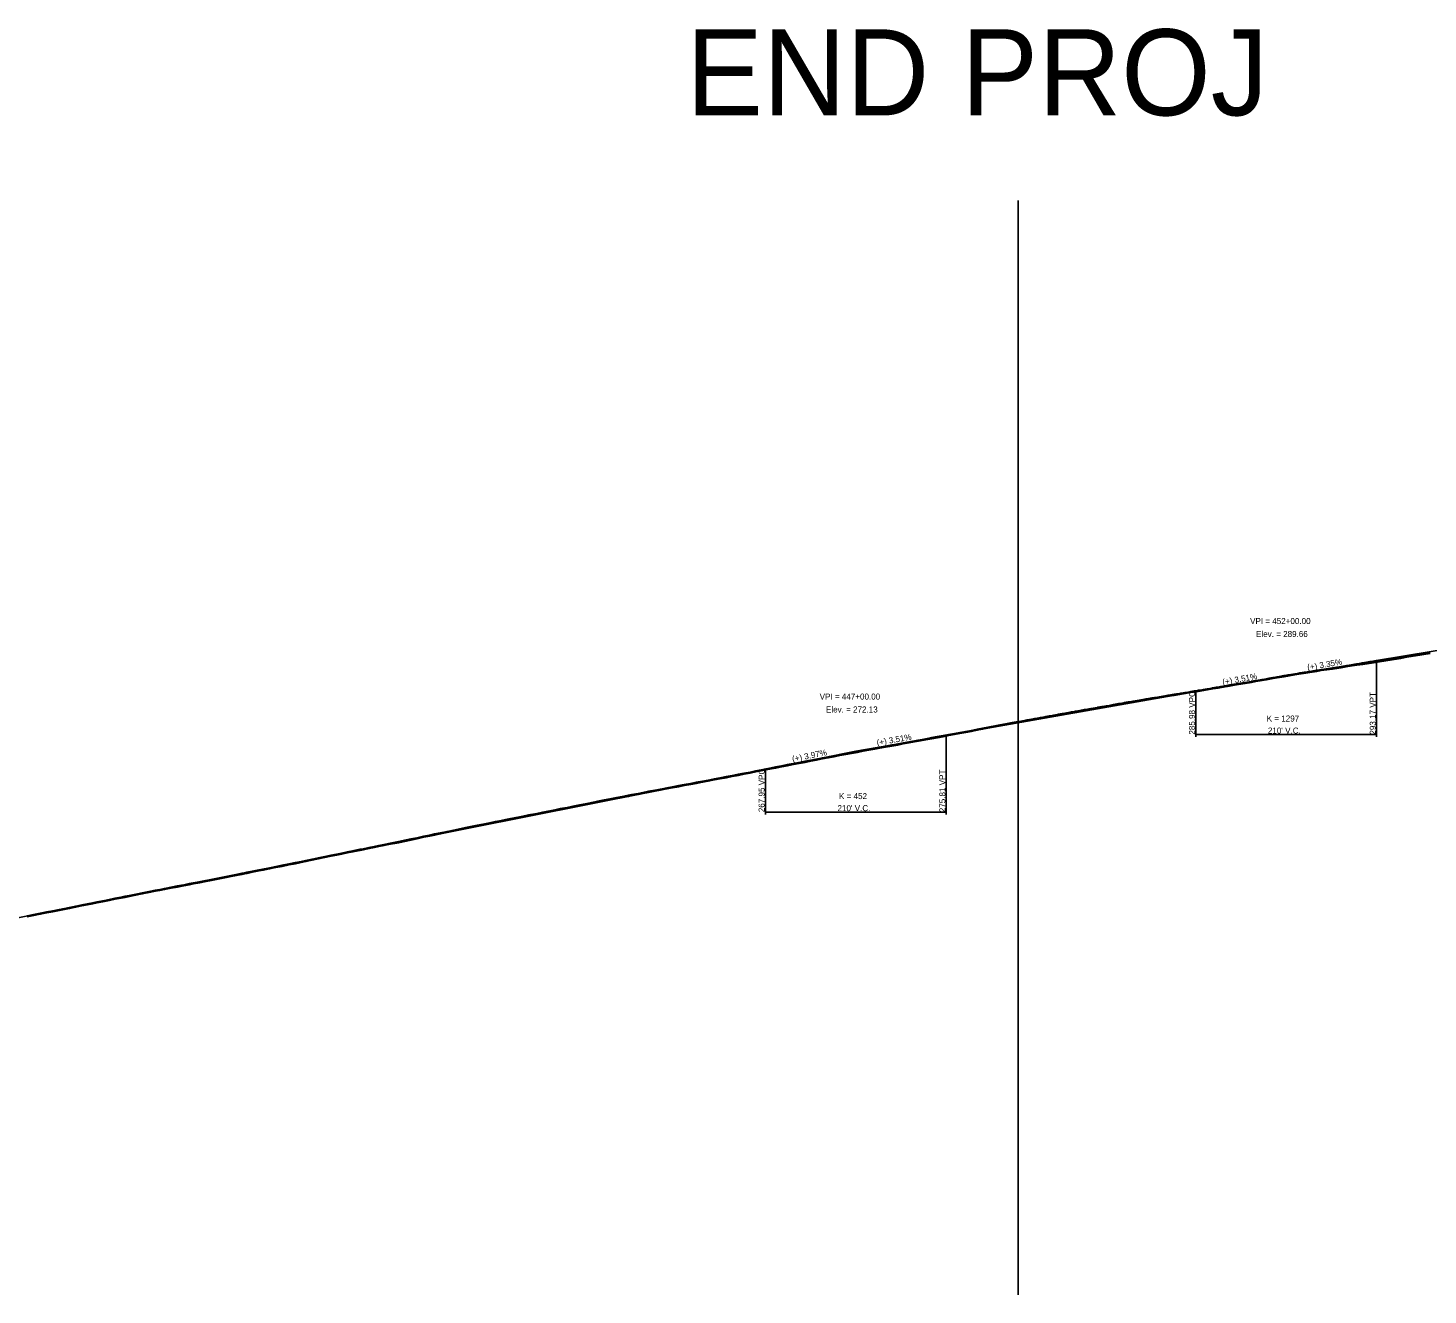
# Model space of a CAD drawing. Extents: x 1876258 to 1926563, y 729739 to 834437.
# Drawn here: x 1922101 to 1923728, y 830733 to 832205 of the extents above; entities that cross this region are included whole.
import ezdxf

# ---------------------------------------------------------------- set-up
doc = ezdxf.new("R2010")
doc.units = 0
for name, color, linetype in [('RD_EX_BldgApp', 7, 'Continuous'), ('RD_EX_H2O_BlueLn', 7, 'Continuous'), ('RD_EX_RailRoad', 7, 'Continuous'), ('RD_HC_Data', 7, 'Continuous'), ('RD_HC_Data_Tic', 7, 'Continuous'), ('RD_HC_TX_Sta50', 7, 'Continuous'), ('RD_PD_ALT5_CL', 7, 'Continuous')]:
    doc.layers.add(name, color=color, linetype=linetype)

msp = doc.modelspace()

# ---------------------------------------------------------------- linework, layer by layer
at = {"layer": 'RD_EX_BldgApp'}
for points in [[(1923224.9, 831393.3), (1923230.6, 831394.3), (1923239.1, 831395.8), (1923245, 831396.9), (1923252, 831398.1), (1923252.1, 831398.2), (1923258, 831399.2), (1923265.1, 831400.5), (1923271.1, 831401.6), (1923278.2, 831402.9), (1923284.1, 831404), (1923291.3, 831405.3), (1923297.4, 831406.4), (1923304.4, 831407.7), (1923310.5, 831408.8), (1923317.5, 831410), (1923323.4, 831411), (1923330.5, 831412.3), (1923336.7, 831413.4), (1923343.6, 831414.7), (1923350.1, 831415.7), (1923355.6, 831416.5), (1923362.1, 831417.7), (1923368.6, 831418.9), (1923375.2, 831420.1), (1923381.4, 831421.2), (1923388.1, 831422.3), (1923394.3, 831423.4), (1923400.9, 831424.5), (1923407.2, 831425.5), (1923413.7, 831426.6), (1923420.1, 831427.6), (1923426.6, 831428.8), (1923432.9, 831429.8), (1923439.5, 831430.9), (1923445.8, 831431.9), (1923452.3, 831433), (1923458.7, 831434), (1923465.2, 831435.1), (1923471.6, 831436.1), (1923477.8, 831437.2), (1923484, 831438.3), (1923490, 831439.3), (1923497.3, 831440.6), (1923502.8, 831441.6), (1923510, 831442.7), (1923515.2, 831443.7), (1923522.6, 831444.9), (1923527.6, 831445.8), (1923535.2, 831447.1), (1923540.1, 831448), (1923547.8, 831449.3), (1923552.7, 831450.2), (1923560.5, 831451.5), (1923565.1, 831452.2), (1923573.1, 831453.6), (1923577.8, 831454.4), (1923585.8, 831455.7), (1923590.6, 831456.4), (1923598.6, 831457.7), (1923603.8, 831458.5), (1923616.9, 831460.4), (1923626.8, 831461.9), (1923634.8, 831463.2), (1923644.9, 831464.7), (1923652, 831465.8), (1923662, 831467.3), (1923669.1, 831468.4), (1923678.9, 831469.9), (1923686.2, 831471.1), (1923696.1, 831472.7), (1923703.3, 831474), (1923713.3, 831475.6), (1923720.5, 831476.7), (1923730.3, 831478.3)], [(1922539, 831260.2), (1922546.6, 831261.8), (1922553.5, 831263.3), (1922561.2, 831264.9), (1922568.1, 831266.3), (1922573.9, 831267.5), (1922580.7, 831268.9), (1922588.4, 831270.5), (1922596.2, 831272.1), (1922609.8, 831274.9), (1922615.6, 831276.1), (1922623.4, 831277.6), (1922630.1, 831279), (1922637.8, 831280.6), (1922644.3, 831281.8), (1922649.6, 831283), (1922656.3, 831284.3), (1922662.2, 831285.5), (1922668.7, 831286.8), (1922676.6, 831288.4), (1922683.1, 831289.7), (1922692.8, 831291.5), (1922699.4, 831292.8), (1922705.9, 831294), (1922713.7, 831295.6), (1922720, 831296.9), (1922728, 831298.5), (1922734.5, 831299.8), (1922742.3, 831301.4), (1922748.8, 831302.6), (1922756.7, 831304.2), (1922763.2, 831305.6), (1922770.9, 831307.1), (1922777.6, 831308.4), (1922785.3, 831310), (1922791.8, 831311.2), (1922798.9, 831312.5), (1922802.8, 831313.3), (1922810.5, 831314.8), (1922815.9, 831315.8), (1922822.4, 831317.1), (1922829.8, 831318.5), (1922836.3, 831319.7), (1922843.6, 831321.1), (1922850.2, 831322.4), (1922857.4, 831323.7), (1922864, 831325), (1922871.3, 831326.3), (1922877.9, 831327.5), (1922885.1, 831328.9), (1922891.7, 831330.2), (1922899, 831331.7), (1922905.6, 831332.9), (1922912.8, 831334.2), (1922919.5, 831335.5), (1922926.7, 831336.8), (1922933.3, 831338.1), (1922940.5, 831339.5), (1922946.9, 831340.8), (1922953.3, 831342.1), (1922957, 831342.8), (1922965.1, 831344.4), (1922970.1, 831345.4), (1922977, 831346.8), (1922983.6, 831348.1), (1922990.6, 831349.5), (1922997.2, 831350.7), (1923004.1, 831352), (1923010.8, 831353.3), (1923017.5, 831354.6), (1923024.2, 831355.9), (1923031.1, 831357.2), (1923037.8, 831358.5), (1923044.5, 831359.8), (1923051.3, 831361.1), (1923058.2, 831362.4), (1923064.9, 831363.6), (1923071.7, 831364.9), (1923078.3, 831366.1), (1923085.1, 831367.3), (1923090.9, 831368.4), (1923097.4, 831369.6), (1923105, 831370.9), (1923111.7, 831372.1), (1923118.2, 831373.4), (1923125, 831374.5), (1923131.4, 831375.7), (1923138.1, 831376.9), (1923144.6, 831378.2), (1923151.3, 831379.4), (1923157.8, 831380.6), (1923164.6, 831381.8), (1923171, 831383), (1923177.8, 831384.3), (1923184.1, 831385.5), (1923191, 831386.7), (1923197.3, 831387.9), (1923204.2, 831389.2), (1923210.4, 831390.4), (1923218.6, 831392), (1923224.9, 831393.3)], [(1922100.6, 831172.6), (1922108.1, 831174.1), (1922115.6, 831175.5), (1922123.3, 831177.1), (1922130.4, 831178.5), (1922136.2, 831179.6), (1922142.1, 831180.8), (1922149.7, 831182.2), (1922157.2, 831183.8), (1922164, 831185.2), (1922170.5, 831186.5), (1922176.8, 831187.7), (1922181.7, 831188.7), (1922188.5, 831190), (1922196.1, 831191.5), (1922202.7, 831192.9), (1922209.6, 831194.2), (1922214.2, 831195.1), (1922219.3, 831196.2), (1922226.9, 831197.7), (1922234.2, 831199.1), (1922242.1, 831200.7), (1922249.4, 831202.2), (1922254.6, 831203.2), (1922260.2, 831204.3), (1922267.7, 831205.8), (1922275.1, 831207.2), (1922282.5, 831208.6), (1922289, 831209.8), (1922293.7, 831210.8), (1922301, 831212.2), (1922308.6, 831213.6), (1922314.7, 831214.8), (1922322.3, 831216.3), (1922330, 831217.9), (1922341.5, 831220.1), (1922350.1, 831221.9), (1922353.4, 831222.6), (1922355.9, 831223), (1922362.2, 831224.3), (1922369.9, 831225.8), (1922374.9, 831226.9), (1922382.1, 831228.3), (1922389.5, 831229.8), (1922396.7, 831231.2), (1922404.8, 831232.9), (1922412, 831234.3), (1922417.1, 831235.4), (1922424.2, 831236.8), (1922431.7, 831238.4), (1922438.9, 831239.8), (1922446.3, 831241.4), (1922453.7, 831242.9), (1922460.3, 831244.2), (1922466, 831245.4), (1922472.5, 831246.8), (1922478.8, 831248), (1922487.2, 831249.7), (1922491, 831250.5), (1922497.8, 831251.8), (1922503.8, 831253), (1922508.8, 831254.1), (1922515.2, 831255.4), (1922520.4, 831256.4), (1922532.1, 831258.7), (1922539, 831260.2)]]:
    msp.add_lwpolyline(points, dxfattribs=at)
at = {"layer": 'RD_EX_H2O_BlueLn'}
for p, q in [((1923668.1, 831381.7), (1923668.1, 831470.2)), ((1923458.1, 831381.7), (1923458.1, 831434.2)), ((1923168.1, 831291.6), (1923168.1, 831383.3)), ((1923458.1, 831384.2), (1923668.1, 831384.2)), ((1922958.1, 831291.6), (1922958.1, 831344.1)), ((1922958.1, 831294.1), (1923168.1, 831294.1))]:
    msp.add_line(p, q, dxfattribs=at)
at = {"layer": 'RD_HC_Data_Tic'}
msp.add_line((1923251.7, 830733.3), (1923251.7, 832004.8), dxfattribs=at)
msp.add_lwpolyline([(1922100.3, 831173.8), (1922107.9, 831175.3), (1922115.4, 831176.8), (1922123, 831178.3), (1922130.2, 831179.7), (1922135.9, 831180.8), (1922141.8, 831182), (1922149.4, 831183.4), (1922157, 831185), (1922163.8, 831186.4), (1922170.3, 831187.7), (1922176.5, 831189), (1922181.4, 831189.9), (1922188.3, 831191.3), (1922195.8, 831192.7), (1922202.5, 831194.1), (1922209.4, 831195.5), (1922213.9, 831196.4), (1922219, 831197.4), (1922226.6, 831198.9), (1922234, 831200.4), (1922241.9, 831201.9), (1922249.1, 831203.4), (1922254.4, 831204.4), (1922259.9, 831205.6), (1922267.5, 831207), (1922274.8, 831208.4), (1922282.3, 831209.8), (1922288.7, 831211.1), (1922293.5, 831212), (1922300.8, 831213.4), (1922308.4, 831214.8), (1922314.5, 831216), (1922322, 831217.5), (1922329.8, 831219.1), (1922341.3, 831221.4), (1922349.9, 831223.1), (1922353.2, 831223.8), (1922355.7, 831224.3), (1922362, 831225.5), (1922369.6, 831227), (1922374.6, 831228.1), (1922381.8, 831229.5), (1922389.3, 831231), (1922396.5, 831232.5), (1922404.5, 831234.1), (1922411.7, 831235.5), (1922416.8, 831236.6), (1922423.9, 831238), (1922431.4, 831239.6), (1922438.6, 831241.1), (1922446.1, 831242.6), (1922453.4, 831244.1), (1922460, 831245.4), (1922465.7, 831246.6), (1922472.3, 831248), (1922478.5, 831249.2), (1922486.9, 831251), (1922490.7, 831251.7), (1922497.5, 831253.1), (1922503.6, 831254.2), (1922508.6, 831255.3), (1922515, 831256.6), (1922520.1, 831257.6), (1922531.8, 831260), (1922538.8, 831261.5), (1922546.3, 831263), (1922553.3, 831264.5), (1922560.9, 831266.1), (1922567.8, 831267.5), (1922573.7, 831268.8), (1922580.4, 831270.1), (1922588.2, 831271.8), (1922595.9, 831273.3), (1922609.6, 831276.2), (1922615.3, 831277.3), (1922623.1, 831278.9), (1922629.9, 831280.2), (1922637.6, 831281.8), (1922644.1, 831283.1), (1922649.3, 831284.2), (1922656.1, 831285.5), (1922662, 831286.7), (1922668.5, 831288.1), (1922676.3, 831289.6), (1922682.9, 831290.9), (1922692.6, 831292.7), (1922699.1, 831294), (1922705.6, 831295.3), (1922713.4, 831296.8), (1922719.8, 831298.2), (1922727.7, 831299.7), (1922734.3, 831301.1), (1922742.1, 831302.6), (1922748.6, 831303.9), (1922756.4, 831305.5), (1922762.9, 831306.8), (1922770.7, 831308.3), (1922777.3, 831309.6), (1922785.1, 831311.2), (1922791.6, 831312.4), (1922798.6, 831313.7), (1922802.5, 831314.5), (1922810.3, 831316), (1922815.7, 831317.1), (1922822.2, 831318.4), (1922829.5, 831319.7), (1922836.1, 831321), (1922843.4, 831322.3), (1922849.9, 831323.6), (1922857.2, 831325), (1922863.8, 831326.2), (1922871.1, 831327.5), (1922877.6, 831328.8), (1922884.9, 831330.1), (1922891.4, 831331.4), (1922898.7, 831332.9), (1922905.3, 831334.2), (1922912.6, 831335.5), (1922919.3, 831336.7), (1922926.5, 831338.1), (1922933.1, 831339.3), (1922940.2, 831340.7), (1922946.7, 831342), (1922953, 831343.3), (1922956.8, 831344), (1922964.9, 831345.6), (1922969.8, 831346.6), (1922976.8, 831348), (1922983.4, 831349.4), (1922990.4, 831350.7), (1922996.9, 831352), (1923003.9, 831353.3), (1923010.6, 831354.6), (1923017.3, 831355.8), (1923024, 831357.1), (1923030.9, 831358.4), (1923037.5, 831359.7), (1923044.3, 831361), (1923051.1, 831362.3), (1923057.9, 831363.6), (1923064.6, 831364.9), (1923071.5, 831366.1), (1923078.1, 831367.3), (1923084.9, 831368.6), (1923090.7, 831369.6), (1923097.2, 831370.8), (1923104.8, 831372.2), (1923111.5, 831373.3), (1923118, 831374.6), (1923124.7, 831375.8), (1923131.2, 831376.9), (1923137.9, 831378.1), (1923144.3, 831379.4), (1923151.1, 831380.7), (1923157.6, 831381.9), (1923164.4, 831383.1), (1923170.7, 831384.2), (1923177.6, 831385.5), (1923183.9, 831386.7), (1923190.7, 831388), (1923197, 831389.1), (1923204, 831390.4), (1923210.2, 831391.6), (1923218.4, 831393.3), (1923224.7, 831394.5), (1923230.4, 831395.5), (1923238.8, 831397.1), (1923244.7, 831398.1), (1923251.8, 831399.4), (1923251.9, 831399.4), (1923257, 831400.3), (1923257.8, 831400.4), (1923262.1, 831401.2), (1923264.9, 831401.8), (1923267.2, 831402.2), (1923270.8, 831402.8), (1923272.3, 831403.1), (1923277.4, 831404), (1923278, 831404.2), (1923282.5, 831405), (1923283.9, 831405.2), (1923287.6, 831405.9), (1923291.1, 831406.5), (1923292.7, 831406.8), (1923297.2, 831407.6), (1923297.8, 831407.8), (1923302.9, 831408.7), (1923304.1, 831408.9), (1923308, 831409.6), (1923310.2, 831410), (1923313.2, 831410.5), (1923317.3, 831411.2), (1923318.3, 831411.4), (1923323.2, 831412.2), (1923323.4, 831412.3), (1923328.5, 831413.2), (1923330.3, 831413.5), (1923333.6, 831414.1), (1923336.4, 831414.6), (1923338.7, 831415), (1923343.4, 831415.9), (1923343.8, 831416), (1923348.9, 831416.8), (1923349.9, 831416.9), (1923354, 831417.6), (1923355.4, 831417.8), (1923359.1, 831418.5), (1923361.9, 831419), (1923364.2, 831419.4), (1923368.3, 831420.2), (1923369.3, 831420.3), (1923374.4, 831421.3), (1923375, 831421.4), (1923379.6, 831422.1), (1923381.2, 831422.4), (1923384.7, 831423), (1923387.9, 831423.6), (1923389.8, 831423.9), (1923394.1, 831424.6), (1923394.9, 831424.8), (1923400, 831425.6), (1923400.7, 831425.8), (1923405.1, 831426.5), (1923407, 831426.8), (1923410.2, 831427.3), (1923413.5, 831427.8), (1923415.3, 831428.1), (1923419.9, 831428.9), (1923420.4, 831429), (1923425.5, 831429.9), (1923426.4, 831430), (1923430.6, 831430.7), (1923432.7, 831431.1), (1923435.7, 831431.6), (1923439.3, 831432.1), (1923440.8, 831432.4), (1923445.6, 831433.2), (1923445.9, 831433.2), (1923451, 831434.1), (1923452.1, 831434.2), (1923456.2, 831434.9), (1923458.5, 831435.2), (1923461.3, 831435.7), (1923465, 831436.3), (1923466.4, 831436.5), (1923471.3, 831437.3), (1923471.5, 831437.3), (1923476.6, 831438.3), (1923477.5, 831438.4), (1923481.7, 831439.2), (1923483.8, 831439.5), (1923486.8, 831440.1), (1923489.8, 831440.6), (1923491.9, 831440.9), (1923497, 831441.9), (1923497.1, 831441.9), (1923502.1, 831442.8), (1923502.6, 831442.9), (1923507.2, 831443.6), (1923509.7, 831444), (1923512.3, 831444.4), (1923515, 831444.9), (1923517.4, 831445.3), (1923522.4, 831446.1), (1923522.5, 831446.2), (1923527.4, 831447), (1923527.6, 831447), (1923532.7, 831447.9), (1923534.9, 831448.3), (1923537.9, 831448.8), (1923539.9, 831449.2), (1923543, 831449.7), (1923547.6, 831450.5), (1923548.1, 831450.6), (1923552.5, 831451.4), (1923553.2, 831451.5), (1923558.3, 831452.4), (1923560.3, 831452.7), (1923563.4, 831453.2), (1923564.9, 831453.5), (1923568.5, 831454.1), (1923572.9, 831454.8), (1923573.6, 831454.9), (1923577.6, 831455.6), (1923578.7, 831455.8), (1923583.8, 831456.6), (1923585.6, 831456.9), (1923588.9, 831457.4), (1923590.4, 831457.7), (1923594, 831458.3), (1923598.4, 831458.9), (1923599.2, 831459.1), (1923603.6, 831459.7), (1923604.3, 831459.8), (1923609.4, 831460.6), (1923614.5, 831461.3), (1923616.8, 831461.6), (1923619.6, 831462.1), (1923624.7, 831462.9), (1923626.6, 831463.1), (1923629.8, 831463.7), (1923634.6, 831464.4), (1923634.9, 831464.5), (1923640, 831465.2), (1923644.8, 831466), (1923645.1, 831466), (1923650.2, 831466.8), (1923651.8, 831467), (1923655.3, 831467.6), (1923660.4, 831468.3), (1923661.8, 831468.5), (1923665.5, 831469.1), (1923669, 831469.7), (1923670.7, 831469.9), (1923675.8, 831470.7), (1923678.7, 831471.1), (1923680.8, 831471.5), (1923686, 831472.3), (1923686, 831472.3), (1923691.1, 831473.2), (1923695.9, 831473.9), (1923696.2, 831474), (1923701.3, 831474.9), (1923703.1, 831475.2), (1923706.4, 831475.7), (1923711.5, 831476.5), (1923713.1, 831476.8), (1923716.6, 831477.4), (1923720.3, 831477.9), (1923721.7, 831478.2), (1923726.8, 831479), (1923730.1, 831479.5)], dxfattribs=at)
at = {"layer": 'RD_HC_TX_Sta50'}
for p, q in [((1923484.3, 831438.8), (1923563.1, 831452.6)), ((1923642, 831465.8), (1923563.1, 831452.6)), ((1923141.9, 831378.7), (1923063.1, 831364.9)), ((1922984.6, 831349.3), (1923063.1, 831364.9))]:
    msp.add_line(p, q, dxfattribs=at)
at = {"layer": 'RD_PD_ALT5_CL'}
for p, q in [((1923668.1, 831470.2), (1924298.1, 831575.6)), ((1923168.1, 831383.3), (1923458.1, 831434.2)), ((1922068.1, 831167.3), (1922958.1, 831344.1))]:
    msp.add_line(p, q, dxfattribs=at)
for points in [[(1923458.1, 831434.2), (1923462.3, 831434.9), (1923466.5, 831435.7), (1923470.7, 831436.4), (1923474.9, 831437.1), (1923479.1, 831437.9), (1923483.3, 831438.6), (1923487.5, 831439.3), (1923491.7, 831440.1), (1923495.9, 831440.8), (1923500.1, 831441.5), (1923504.3, 831442.3), (1923508.5, 831443), (1923512.7, 831443.7), (1923516.9, 831444.4), (1923521.1, 831445.2), (1923525.3, 831445.9), (1923529.5, 831446.6), (1923533.7, 831447.3), (1923537.9, 831448.1), (1923542.1, 831448.8), (1923546.3, 831449.5), (1923550.5, 831450.2), (1923554.7, 831451), (1923558.9, 831451.7), (1923563.1, 831452.4), (1923567.3, 831453.1), (1923571.5, 831453.8), (1923575.7, 831454.5), (1923579.9, 831455.3), (1923584.1, 831456), (1923588.3, 831456.7), (1923592.5, 831457.4), (1923596.7, 831458.1), (1923600.9, 831458.8), (1923605.1, 831459.6), (1923609.3, 831460.3), (1923613.5, 831461), (1923617.7, 831461.7), (1923621.9, 831462.4), (1923626.1, 831463.1), (1923630.3, 831463.8), (1923634.5, 831464.5), (1923638.7, 831465.2), (1923642.9, 831465.9), (1923647.1, 831466.6), (1923651.3, 831467.4), (1923655.5, 831468.1), (1923659.7, 831468.8), (1923663.9, 831469.5), (1923668.1, 831470.2)], [(1922958.1, 831344.1), (1922962.3, 831344.9), (1922966.5, 831345.7), (1922970.7, 831346.6), (1922974.9, 831347.4), (1922979.1, 831348.2), (1922983.3, 831349), (1922987.5, 831349.9), (1922991.7, 831350.7), (1922995.9, 831351.5), (1923000.1, 831352.3), (1923004.3, 831353.1), (1923008.5, 831353.9), (1923012.7, 831354.7), (1923016.9, 831355.6), (1923021.1, 831356.4), (1923025.3, 831357.2), (1923029.5, 831358), (1923033.7, 831358.8), (1923037.9, 831359.6), (1923042.1, 831360.4), (1923046.3, 831361.2), (1923050.5, 831361.9), (1923054.7, 831362.7), (1923058.9, 831363.5), (1923063.1, 831364.3), (1923067.3, 831365.1), (1923071.5, 831365.9), (1923075.7, 831366.7), (1923079.9, 831367.4), (1923084.1, 831368.2), (1923088.3, 831369), (1923092.5, 831369.8), (1923096.7, 831370.5), (1923100.9, 831371.3), (1923105.1, 831372.1), (1923109.3, 831372.8), (1923113.5, 831373.6), (1923117.7, 831374.4), (1923121.9, 831375.1), (1923126.1, 831375.9), (1923130.3, 831376.6), (1923134.5, 831377.4), (1923138.7, 831378.1), (1923142.9, 831378.9), (1923147.1, 831379.6), (1923151.3, 831380.4), (1923155.5, 831381.1), (1923159.7, 831381.9), (1923163.9, 831382.6), (1923168.1, 831383.3)]]:
    msp.add_spline(points, degree=3, dxfattribs=at)

# ---------------------------------------------------------------- texts
at = {"layer": 'RD_EX_H2O_BlueLn'}
for s, p in [('K = 1297', (1923540.4, 831399.4)), ("210' V.C.", (1923541.8, 831385.4)), ('K = 452', (1923043.6, 831309.3)), ("210' V.C.", (1923041.8, 831295.3))]:
    msp.add_text(s, height=7, dxfattribs=at).set_placement(p)
at = {"layer": 'RD_EX_RailRoad'}
for s, p in [('285.98 VPC', (1923457.1, 831384.2)), ('293.17 VPT', (1923667.1, 831384.2)), ('267.95 VPC', (1922957.1, 831294.1)), ('275.81 VPT', (1923167.1, 831294.1))]:
    msp.add_text(s, height=7, rotation=90, dxfattribs=at).set_placement(p)
at = {"layer": 'RD_HC_Data'}
for s, p in [('VPI = 452+00.00', (1923521.1, 831512.6)), ('Elev. = 289.66', (1923528, 831497.6)), ('VPI = 447+00.00', (1923021.1, 831424.9)), ('Elev. = 272.13', (1923028.4, 831409.9))]:
    msp.add_text(s, height=7, dxfattribs=at).set_placement(p)
at = {"layer": 'RD_HC_Data_Tic'}
msp.add_text('END PROJ', height=100, dxfattribs=at).set_placement((1922866.1, 832103.5))
at = {"layer": 'RD_HC_TX_Sta50'}
for s, rotation, p in [('(+) 3.35%', 9.4961, (1923588.1, 831458.8)), ('(+) 3.51%', 9.9468, (1923489.5, 831441.7)), ('(+) 3.51%', 9.9468, (1923088, 831371.3)), ('(+) 3.97%', 11.2327, (1922989.8, 831352.4))]:
    msp.add_text(s, height=7, rotation=rotation, dxfattribs=at).set_placement(p)

doc.saveas('drawing.dxf')
